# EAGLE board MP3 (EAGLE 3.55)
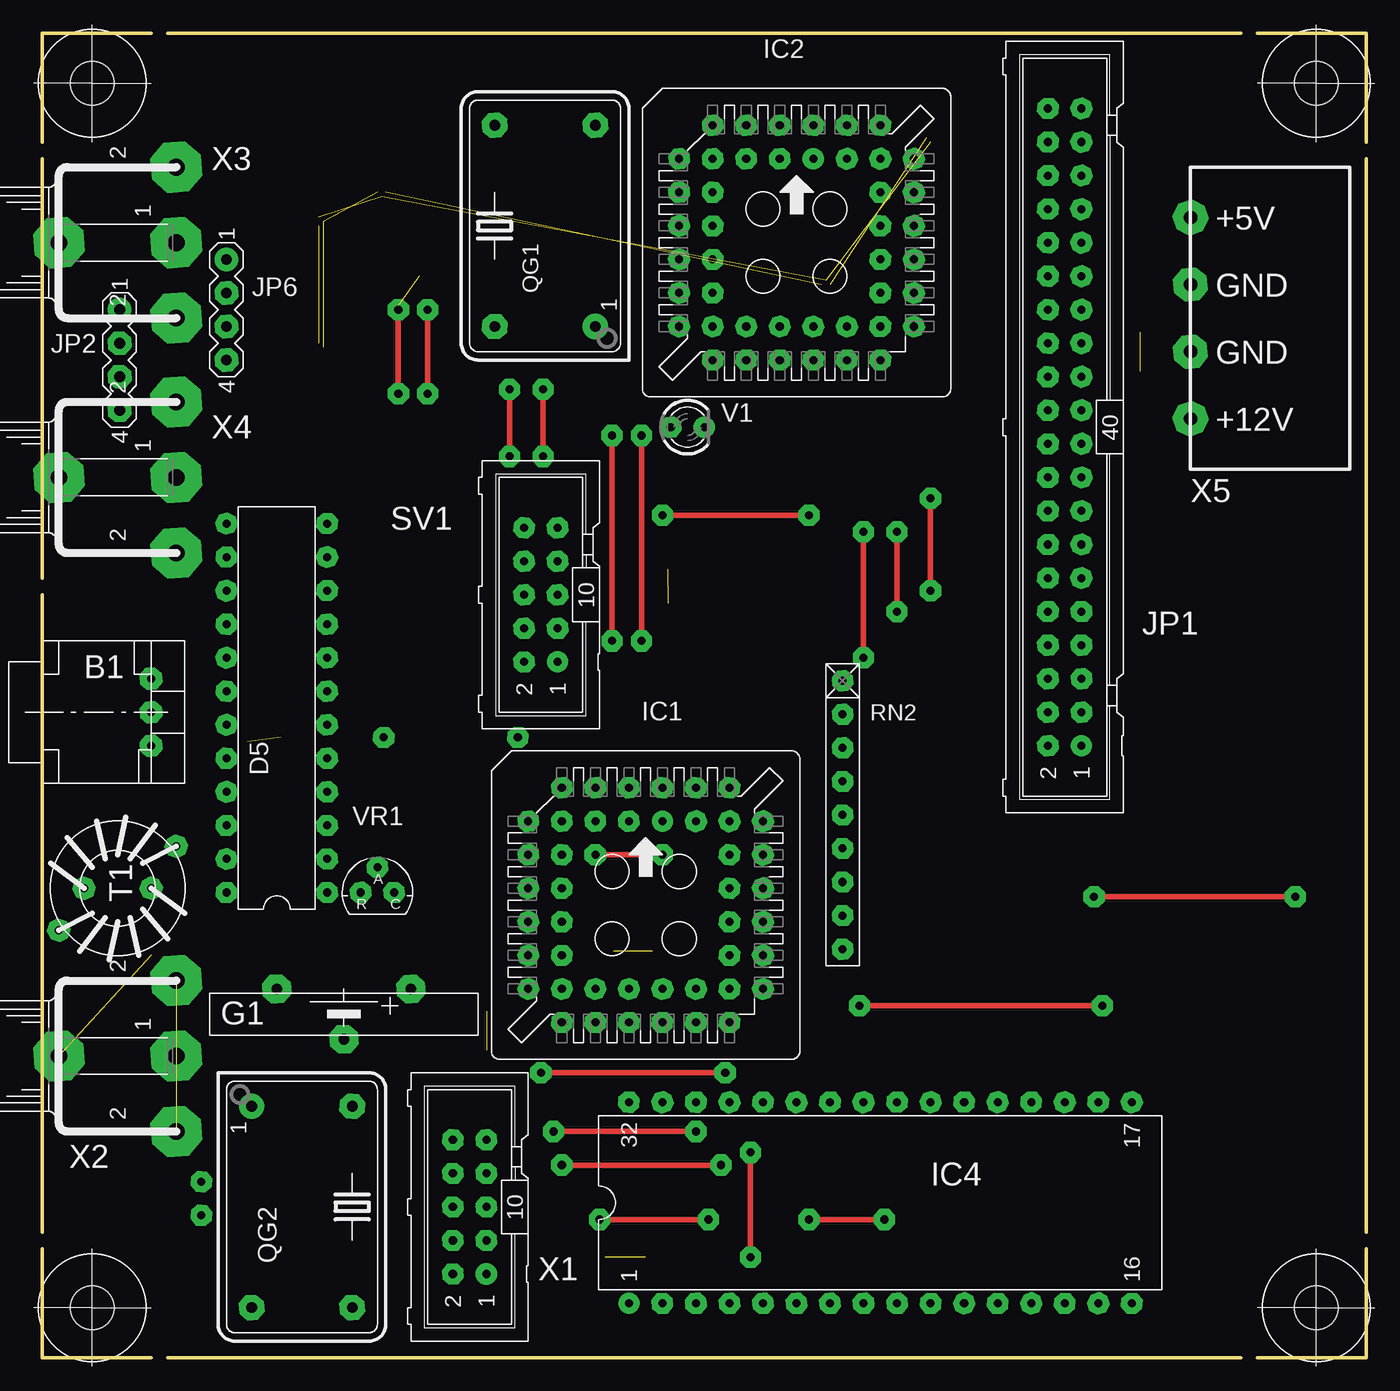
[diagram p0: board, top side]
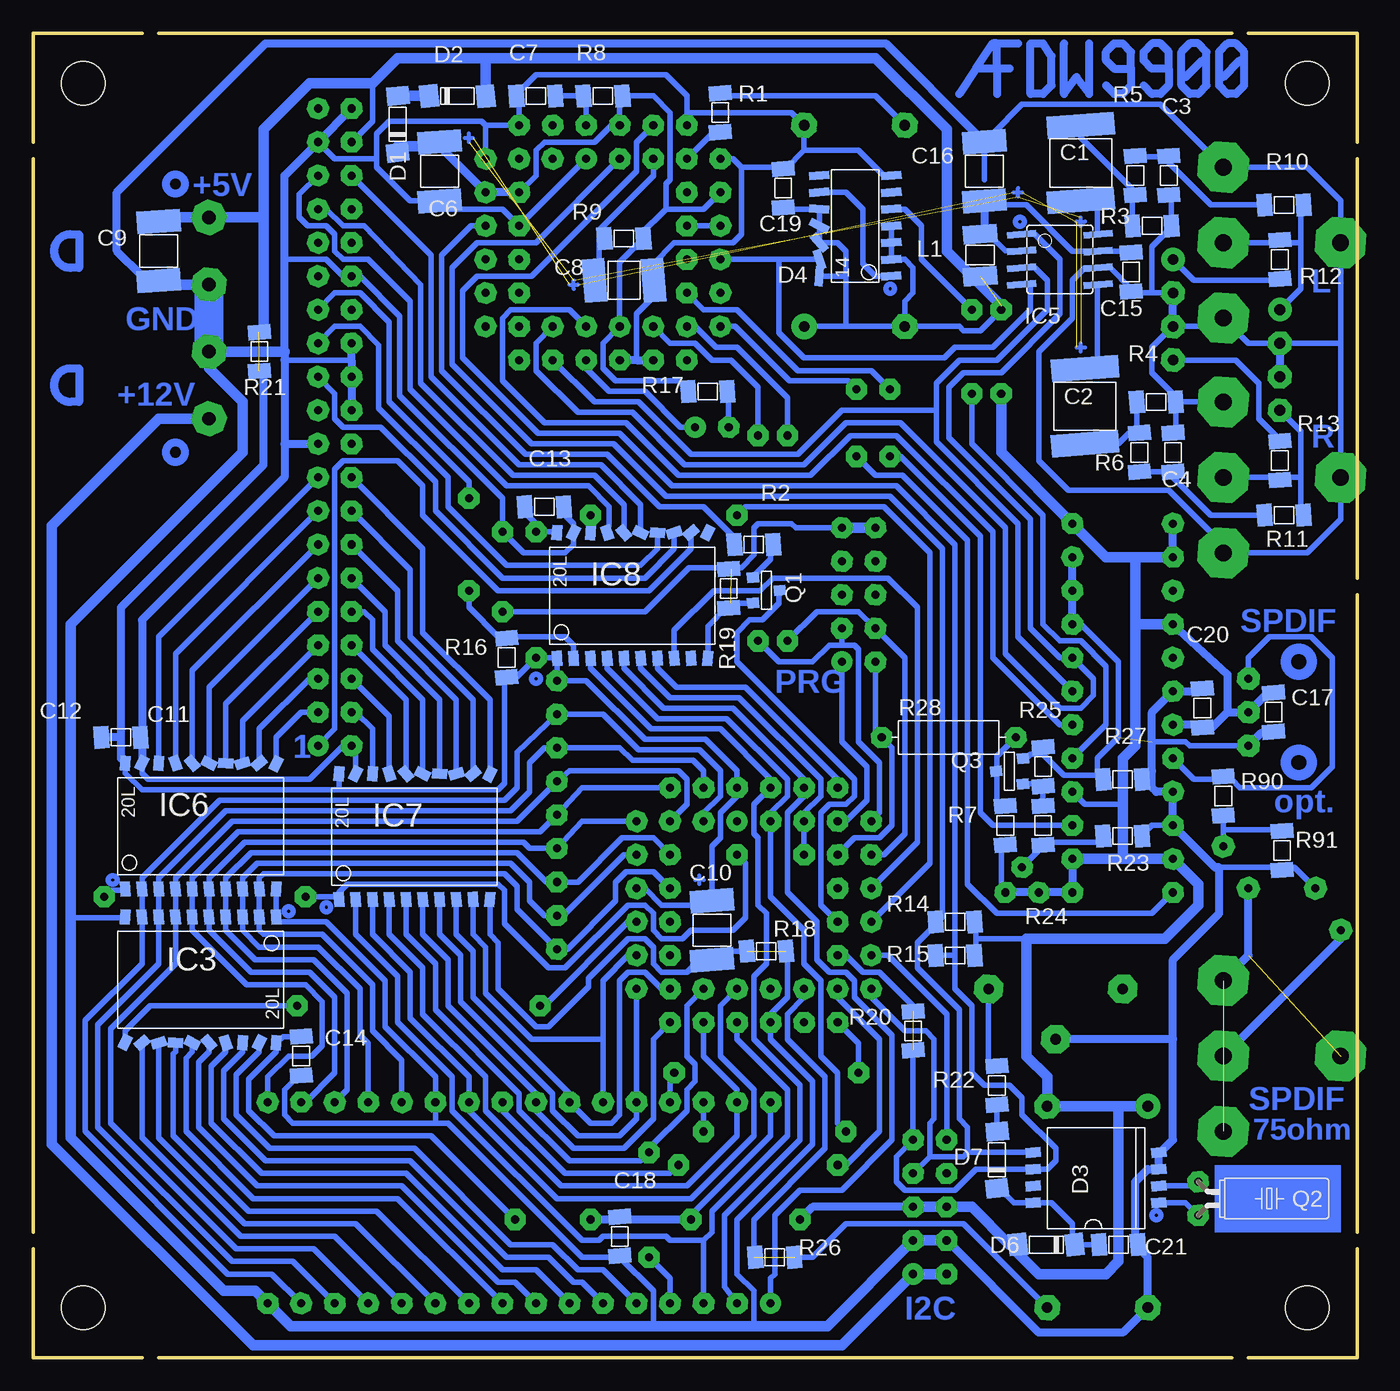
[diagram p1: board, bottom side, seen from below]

Size 100.33 x 100.33 mm. Coordinates in mm from the lower left corner, seen from the top.
Outline: 8.26,0 0,0 0,8.26
Outline: 9.53,0 90.8,0
Outline: 92.07,0 100.33,0 100.33,8.26
Outline: 100.33,9.53 100.33,90.81
Outline: 100.33,92.08 100.33,100.33 92.07,100.33
Outline: 90.8,100.33 9.53,100.33
Outline: 8.26,100.33 0,100.33 0,92.08
Outline: 0,90.81 0,59.05
Outline: 0,57.78 0,9.53
Copper layers used: Top, Bottom

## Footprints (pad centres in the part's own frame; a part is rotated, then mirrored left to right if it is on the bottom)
TX178 = drill 0.61 pad 1.676 octagon:  -2.54,0;  0,0;  2.54,0
20 = smd 1.702 x 5.105 rotated 4.4:  2.845,0 | smd 1.702 x 5.105 rotated 4.3:  -2.845,0
06 = smd 1.143 x 1.702 rotated 4.4:  1.473,0 | smd 1.143 x 1.702 rotated 4.3:  -1.473,0
12 = smd 1.702 x 3.302 rotated 4.4:  2.235,0 | smd 1.702 x 3.302 rotated 4.3:  -2.235,0
D80 = smd 1.397 x 1.702 rotated 6.6:  -2.388,0 | smd 1.397 x 1.702 rotated 5.7:  1.905,-0.025
T176-1 = smd 0.762 x 1.143 rotated 4.3:  -1.905,-4.648 | smd 0.762 x 1.143 rotated 4.4:  -0.635,-4.648 | smd 0.762 x 1.143 rotated 4.5:  0.635,-4.648 | smd 0.762 x 1.143 rotated 4.6:  1.905,-4.648 | smd 0.762 x 1.143 rotated 4.7:  1.905,4.877;  0.635,4.877 | smd 0.762 x 1.143 rotated 4.8:  -0.635,4.877 | smd 0.762 x 1.143 rotated 4.9:  -1.905,4.877
-14 = smd 0.61 x 1.524 rotated 4.3:  -3.81,-2.794;  1.27,2.667 | smd 0.61 x 1.524 rotated 94.3:  -3.81,2.667 | smd 0.61 x 1.524 rotated 4.4:  -2.54,-2.794 | smd 0.61 x 1.524 rotated 4.5:  -1.27,-2.794 | smd 0.61 x 1.524 rotated 71.8:  -2.54,2.667 | smd 0.61 x 1.524 rotated 49.3:  -1.27,2.667 | smd 0.61 x 1.524 rotated 4.6:  0,-2.794 | smd 0.61 x 1.524 rotated 26.8:  0,2.667 | smd 0.61 x 1.524 rotated 4.7:  1.27,-2.794;  2.54,-2.794 | smd 0.61 x 1.524 rotated 5:  2.54,2.667 | smd 0.61 x 1.524 rotated 4.8:  3.81,-2.794 | smd 0.61 x 1.524 rotated 4.9:  3.81,2.667
L24S = drill 0.61 pad 1.6 octagon:  -12.7,-5.08;  -10.16,-5.08;  2.54,-5.08;  5.08,-5.08;  -7.62,-5.08;  -5.08,-5.08;  0,-5.08;  -2.54,-5.08;  7.62,-5.08;  10.16,-5.08;  12.7,-5.08;  15.24,-5.08;  15.24,2.54;  12.7,2.54;  10.16,2.54;  7.62,2.54;  5.08,2.54;  2.54,2.54;  0,2.54;  -2.54,2.54;  -5.08,2.54;  -7.62,2.54;  -10.16,2.54;  -12.7,2.54
32P-V = drill 0.813 pad 2.159 octagon:  -1.905,0;  1.905,-5.08 | drill 0.813 pad 2.184 octagon:  1.905,5.08
CC44 = drill 0.61 pad 1.6 round:  0,0 | drill 0.61 pad 1.6 octagon:  -2.54,2.54;  -2.54,0;  -5.08,2.54;  -5.08,0;  -7.62,2.54;  -10.16,0;  -7.62,0;  -10.16,-2.54;  -7.62,-2.54;  -10.16,-5.08;  -7.62,-5.08;  -10.16,-7.62;  -7.62,-7.62;  -10.16,-10.16;  -7.62,-10.16;  -10.16,-12.7;  -7.62,-15.24;  -7.62,-12.7;  -5.08,-15.24;  -5.08,-12.7;  -2.54,-15.24;  -2.54,-12.7;  0,-15.24;  0,-12.7;  2.54,-15.24;  2.54,-12.7;  5.08,-15.24;  7.62,-12.7;  5.08,-12.7;  7.62,-10.16;  5.08,-10.16;  7.62,-7.62;  5.08,-7.62;  7.62,-5.08;  5.08,-5.08;  7.62,-2.54;  5.08,-2.54;  7.62,0;  5.08,2.54;  5.08,0;  2.54,2.54;  2.54,0;  0,2.54
-20L = smd 0.762 x 1.143 rotated 4.3:  -5.08,-5.131;  6.35,-5.131 | smd 0.762 x 1.143 rotated 4.4:  -3.81,-5.131;  -5.08,4.394 | smd 0.762 x 1.143 rotated 4.5:  -2.54,-5.131 | smd 0.762 x 1.143 rotated 4.6:  -1.27,-5.131 | smd 0.762 x 1.143 rotated 4.7:  0,-5.131;  1.27,-5.131 | smd 0.762 x 1.143 rotated 4.8:  2.54,-5.131 | smd 0.762 x 1.143 rotated 4.9:  3.81,-5.131 | smd 0.762 x 1.143 rotated 5:  5.08,-5.131 | smd 0.762 x 1.143 rotated 49.3:  5.08,4.394 | smd 0.762 x 1.143 rotated 26.8:  6.35,4.369 | smd 0.762 x 1.143 rotated 71.8:  3.81,4.394 | smd 0.762 x 1.143 rotated 94.3:  2.54,4.394 | smd 0.762 x 1.143 rotated 116.8:  1.27,4.394 | smd 0.762 x 1.143 rotated 139.3:  0,4.394 | smd 0.762 x 1.143 rotated 161.8:  -1.27,4.394 | smd 0.762 x 1.143 rotated 184.3:  -2.54,4.394 | smd 0.762 x 1.143 rotated 206.8:  -3.81,4.394
L32 = drill 0.61 pad 1.6 round:  0,0 | drill 0.61 pad 1.6 octagon:  2.54,0;  5.08,0;  7.62,0;  10.16,0;  12.7,0;  15.24,0;  17.78,0;  20.32,0;  22.86,0;  25.4,0;  27.94,0;  30.48,0;  33.02,0;  35.56,0;  38.1,0;  38.1,15.24;  35.56,15.24;  33.02,15.24;  30.48,15.24;  27.94,15.24;  25.4,15.24;  22.86,15.24;  20.32,15.24;  17.78,15.24;  15.24,15.24;  12.7,15.24;  10.16,15.24;  7.62,15.24;  5.08,15.24;  2.54,15.24;  0,15.24
P-8 = smd 0.5 x 2.2 rotated 4.3:  -1.905,-2.9 | smd 0.5 x 2.2 rotated 4.4:  -0.645,-2.9 | smd 0.5 x 2.2 rotated 4.5:  0.625,-2.9 | smd 0.5 x 2.2 rotated 4.6:  1.895,-2.9 | smd 0.5 x 2.2 rotated 4.9:  -1.905,2.9 | smd 0.5 x 2.2 rotated 4.8:  -0.635,2.9 | smd 0.5 x 2.2 rotated 4.7:  0.635,2.9;  1.905,2.9
40 = drill 0.61 pad 1.6 round:  -24.13,-1.27 | drill 0.61 pad 1.6 octagon:  -24.13,1.27;  -21.59,-1.27;  -21.59,1.27;  -19.05,-1.27;  -19.05,1.27;  -16.51,-1.27;  -16.51,1.27;  -13.97,-1.27;  -13.97,1.27;  -11.43,-1.27;  -11.43,1.27;  -8.89,-1.27;  -8.89,1.27;  -6.35,-1.27;  -6.35,1.27;  -3.81,-1.27;  -3.81,1.27;  -1.27,-1.27;  -1.27,1.27;  1.27,-1.27;  1.27,1.27;  3.81,-1.27;  3.81,1.27;  6.35,-1.27;  6.35,1.27;  8.89,-1.27;  8.89,1.27;  11.43,1.27;  11.43,-1.27;  13.97,-1.27;  13.97,1.27;  16.51,1.27;  16.51,-1.27;  19.05,-1.27;  19.05,1.27;  21.59,1.27;  21.59,-1.27;  24.13,-1.27;  24.13,1.27
04-1 = drill 0.813 pad 1.778 round:  -3.81,0 | drill 0.813 pad 1.778 octagon:  -1.27,0;  1.27,0;  3.81,0
10 = smd 1.397 x 2.591 rotated 4.4:  1.6,0 | smd 1.397 x 2.591 rotated 4.3:  -1.6,0
T23EBC = smd 0.787 x 0.889 rotated 5.8:  0.991,1.016 | smd 0.787 x 0.889 rotated 6.1:  -0.94,1.016 | smd 0.787 x 0.889 rotated 5.9:  0.025,-1.016
38H = drill 0.61 pad 1.6 octagon:  -1.27,0;  1.27,0
L14S = drill 0.813 pad 1.905 round:  -7.62,-3.81 | drill 0.813 pad 1.905 octagon:  7.62,-3.81;  7.62,3.81;  -7.62,3.81
10' = drill 0.61 pad 1.6 octagon:  -5.08,0;  5.08,0
-9 = drill 0.61 pad 1.6 octagon:  -10.16,0;  -7.62,0;  -5.08,0;  -2.54,0;  0,0;  2.54,0;  5.08,0;  7.62,0;  10.16,0
10'' = drill 0.61 pad 1.6 round:  -5.08,-1.27 | drill 0.61 pad 1.6 octagon:  -5.08,1.27;  -2.54,-1.27;  -2.54,1.27;  0,-1.27;  0,1.27;  2.54,-1.27;  2.54,1.27;  5.08,-1.27;  5.08,1.27
TB = drill 0.61 pad 1.676 octagon:  0,2.54;  0,-2.54;  3.175,-4.445;  -3.175,4.445
,3 = hole 3.302: 0,0
D3 = drill 0.61 pad 1.6 octagon:  -1.27,0 | drill 0.61 pad 1.6 round:  1.27,0
92-CLP = drill 0.61 pad 1.6 octagon:  -1.27,0;  0,1.905;  1.27,0
NCH = drill 1.27 pad 3.81 octagon:  0,-8.89;  0,0;  5.715,-8.89;  -5.715,-8.89
W5 = drill 1.016 pad 2.54 octagon: 1 -2.54,-5.08; 2 2.54,-5.08; V 7.62,-5.08;  -7.62,-5.08

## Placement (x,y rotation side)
B1  TOTX178  [TX178]  8.26,48.89 270 top
C1  10æ  [20]  20.95,90.49 90 bottom
C2  10æ  [20]  20.64,72.07 270 bottom
C3  680p  [06]  14.29,89.54 270 bottom
C4  680p  [06]  13.97,68.58 270 bottom
C6  10æ  [12]  69.53,89.85 270 bottom
C7  10n  [06]  62.23,95.57 0 bottom
C8  2æ2  [12]  55.56,81.6 180 bottom
C9  10æ  [12]  90.8,83.82 270 bottom
C10  100n//10u  [12]  48.9,32.38 90 bottom
C11  100n  [06]  93.66,46.99 180 bottom
C12  100n  [06]  93.66,46.99 180 bottom
C13  100n  [06]  61.59,64.45 180 bottom
C14  100n  [06]  80.01,22.86 90 bottom
C15  100n  [06]  17.14,82.23 90 bottom
C16  10æ  [12]  28.26,89.85 90 bottom
C17  100n  [06]  6.35,48.89 270 bottom
C18  100n  [06]  55.88,9.21 90 bottom
C19  100n  [06]  43.5,88.58 270 bottom
C20  100n  [06]  11.75,49.21 270 bottom
C21  100n  [06]  18.1,8.57 180 bottom
D1  1N4148  [D80]  72.71,93.66 90 bottom
D2  1N4148  [D80]  67.94,95.57 0 bottom
D3  PCF8583T  [T176-1]  19.68,13.65 90 bottom
D4  74LS113  [-14]  38.1,85.73 90 bottom
D5  CS8402A  [L24S]  16.51,47.94 90 top
D6  1N4148  [D80]  23.81,8.57 180 bottom
D7  1N4148  [D80]  27.3,15.24 90 bottom
G1  BR2032P-V  [32P-V]  22.86,26.04 90 top
IC1  AT89S8252  [CC44]  46.99,40.64 0 top
IC2  MAS3507D  [CC44]  58.42,90.81 0 top
IC3  74HC573  [-20L]  86.99,28.26 180 bottom
IC4  628128/512  [L32]  44.45,4.13 0 top
IC5  CS4331  [P-8]  22.54,83.19 270 bottom
IC6  74HCT245  [-20L]  88.27,40.64 0 bottom
IC7  74HCT245  [-20L]  72.07,39.85 0 bottom
IC8  74HCT245  [-20L]  55.56,58.1 0 bottom
JP1  IDE_CON  [40]  77.47,70.48 90 top
JP2  OUT  [04-1]  5.87,75.56 270 top
JP6  CD_IN  [04-1]  13.97,79.38 270 top
L1  100æH  [10]  28.57,83.5 90 bottom
Q1  BC548  [T23EBC]  44.77,58.1 90 bottom
Q2  32.768kHz  [38H]  12.06,12.07 270 bottom
Q3  BC548  [T23EBC]  26.35,44.45 270 bottom
QG1  14,318Mhz  [L14S]  38.1,85.73 90 top
QG2  24Mhz  [L14S]  19.68,11.43 270 top
R1  470  [06]  48.26,94.3 270 bottom
R2  10k  [06]  45.72,61.59 0 bottom
R3  56k  [06]  15.56,85.73 0 bottom
R4  56k  [06]  15.24,72.39 180 bottom
R5  2k2  [06]  16.83,89.54 90 bottom
R6  2k2  [06]  16.51,68.58 270 bottom
R7  10k  [06]  26.67,40.32 270 bottom
R8  10k  [06]  57.15,95.57 0 bottom
R9  1k  [06]  55.56,84.77 0 bottom
R10  10k  [06]  5.56,87.31 0 bottom
R11  10k  [06]  5.56,63.82 0 bottom
R12  10k  [06]  5.87,83.19 270 bottom
R13  10k  [06]  5.87,67.95 90 bottom
R14  10k  [06]  30.48,33.02 0 bottom
R15  10k  [06]  30.48,30.48 0 bottom
R16  10k  [06]  64.45,53.02 270 bottom
R17  1k  [06]  49.21,73.18 180 bottom
R18  0  [06]  44.77,30.8 0 bottom
R19  0  [06]  47.62,58.26 270 bottom
R20  0  [06]  33.66,24.77 90 bottom
R21  0  [06]  83.18,76.2 270 bottom
R22  470k  [06]  27.3,20.64 90 bottom
R23  3k3  [06]  17.78,39.53 180 bottom
R24  47k  [06]  23.81,40.32 90 bottom
R25  33k  [06]  23.81,44.77 270 bottom
R26  0  [06]  44.13,7.62 0 bottom
R27  0  [06]  17.78,43.81 0 bottom
R28  10k  [10']  30.96,46.99 0 bottom
R90  390  [06]  10.16,42.54 270 bottom
R91  91  [06]  5.71,38.42 270 bottom
RN2  10k  [-9]  60.64,41.12 270 top
SV1  ML10  [10'']  37.78,57.78 90 top
T1  RIK 10  [TB]  5.71,35.56 270 top
U$3  [,3]  96.52,96.52 0 top
U$4  [,3]  96.52,3.81 0 top
U$5  [,3]  3.81,3.81 0 top
U$6  [,3]  3.81,96.52 0 top
V1  LED 3 gn  [D3]  48.9,70.48 0 top
VR1  TL431CLP  [92-CLP]  25.4,35.24 0 top
X1  ML10  [10'']  32.39,11.43 90 top
X2  RCA  [NCH]  1.27,22.86 90 top
X3  RCA  [NCH]  1.27,84.45 90 top
X4  RCA  [NCH]  1.27,66.67 90 top
X5  PSW5  [W5]  92.07,78.74 270 top

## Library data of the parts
B1 D1-D3 D5 G1 Q1 T1 X2-X5 = walter
C1-C4 C6-C19 L1 R1-R18 R90 R91 = smd
C20 C21 R19-R28 RN2 = DISCRETE
D4 IC3 IC5-IC7 = smd-ic
D6 D7 = diode
IC1 IC2 IC4 = mp3
IC8 = 74XX
JP1 SV1 X1 = con-ml
JP2 JP6 = CON-LSTB
Q2 QG1 QG2 = QUARTZ
Q3 = TRANS-SM
U$3-U$6 = holes
V1 = LED
VR1 = v-reg

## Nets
3,3V: C6. D1. IC2. R8. R9. R17.
24MHZ: IC1. QG2. R26.
+: G1.
+12V: X1. X5.V
/POR: C8. IC2. R9.
A0: IC3. IC4.
A1: IC3. IC4.
A2: IC3. IC4.
A3: IC3. IC4.
A4: IC3. IC4.
A5: IC3. IC4.
A6: IC3. IC4.
A7: IC3. IC4.
AD0: IC1. IC3. IC4. IC6. RN2.
AD1: IC1. IC3. IC4. IC6. RN2.
AD2: IC1. IC3. IC4. IC6. RN2.
AD3: IC1. IC3. IC4. IC6. RN2.
AD4: IC1. IC3. IC4. IC6. RN2.
AD5: IC1. IC3. IC4. IC6. RN2.
AD6: IC1. IC3. IC4. IC6. RN2.
AD7: IC1. IC3. IC4. IC6. RN2.
AD8: IC1. IC4. IC7.
AD9: IC1. IC4. IC7.
AD10: IC1. IC4. IC7.
AD11: IC1. IC4. IC7.
AD12: IC1. IC4. IC7.
AD13: IC1. IC4. IC7.
AD14: IC1. IC4. IC7.
AD15: IC1. IC4. IC7.
AOUT_L: JP2. R10. R12. X3.
AOUT_R: JP2. R11. R13. X4.
CLKI: IC2. R1.
CLKO: D4. IC2. IC5.
DCEN: C7. IC2. R8.
FC0: D5. IC2.
FC1: D5. IC2.
FILT+: C15. C16. IC5. L1.
FSYNC: D5. IC2. IC5.
GND: B1. C3. C4. C6. C7. C8. C9. C10. C11. C12. C13. C14. C15. C16. C17. C18. C19. C20. C21. D3. D4. D5. G1. IC1. IC2. IC3. IC4. IC5. IC6. IC7. IC8. JP1. JP2. JP6. Q1. Q3. QG1. QG2. R3. R4. R18. R19. R23. R25. R27. R91. SV1. T1. X1. X3. X4. X5.1 X5.2
IDE_ADR0: IC1. IC4. IC8.
IDE_ADR1: IC1. IC4. IC8.
IDE_ADR2: IC1. IC4. IC8.
IDE_ICHR: IC1. IC8.
IDE_IOR: IC1. IC6. IC7. IC8.
IDE_IOW: IC1. IC8.
IDE_RES: IC1. IC8.
INT: IC1. X1.
MAS_DEM: IC2. R2.
MAS_SIC: IC1. IC2. SV1.
MAS_SID: IC1. IC2. SV1.
MCK: D4. D5.
MEM_/RD: IC1. IC4.
MEM_/WR: IC1. IC4.
MEM_ALE: IC1. IC3.
MISO: IC1. SV1.
N$1: IC8. JP1.
N$2: IC8. JP1.
N$3: IC8. JP1. R16.
N$4: C1. IC5.
N$5: C2. IC5.
N$6: C1. R3. R5.
N$7: C2. R4. R6.
N$8: C3. R5. R10.
N$9: C4. R6. R11.
N$10: IC7. JP1.
N$12: IC7. JP1.
N$13: IC7. JP1.
N$14: IC7. JP1.
N$15: IC7. JP1.
N$16: IC7. JP1.
N$17: IC2.
N$18: IC1. Q1.
N$19: IC8. JP1.
N$20: IC7. JP1.
N$21: Q1. R2.
N$22: QG1. R1.
N$23: D4.
N$24: IC7. JP1.
N$25: IC6. JP1.
N$26: IC6. JP1.
N$27: IC6. JP1.
N$28: IC6. JP1.
N$29: IC6. JP1.
N$30: IC6. JP1.
N$31: IC6. JP1.
N$32: IC6. JP1.
N$33: IC8. JP1.
N$34: IC8. JP1.
N$35: IC8. JP1.
N$38: D3. Q2.
N$39: D3. Q2.
N$41: D1. D2.
N$42: R23. R24. VR1.
N$44: D7. R22.
N$45: Q3. R24. R25.
N$52: JP6. R12.
N$54: JP6. R13.
N$56: R17. V1.
N$59: R90. R91. T1.
N$61: Q3. R7. R28.
PI8: IC2. V1.
RES: IC1. R28. SV1.
SCK: D5. IC2.
SCL: D3. IC1. IC2. R15. R20. X1.
SDA: D3. IC1. IC2. R14. X1.
SDATA: D5. IC2. IC5.
SPDIF+: T1. X2.
SPDIF-: T1. X2.
TXP: B1. D5. R90.
U_BATT: G1. R22.
U_RTC: C21. D3. D6. D7.
VCC: B1. C9. C10. C11. C12. C13. C14. C17. C18. C19. C20. D2. D4. D5. D6. IC1. IC3. IC4. IC6. IC7. IC8. JP1. L1. QG1. QG2. R7. R14. R15. R16. R21. RN2. VR1. X1. X5.

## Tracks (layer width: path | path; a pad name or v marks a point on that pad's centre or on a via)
3,3V
  Bottom 0.406: 48.26,88.27 49.53,87 52.39,87 | 52.39,87 52.39,88.9 52.07,89.22 52.07,94.3 53.34,95.57 55.68,95.57 55.88,95.57 55.88,93.34 56.52,93.34 57.79,92.08 61.59,92.08 62.23,91.44 62.23,89.54 63.5,88.27 | 52.39,87 54.29,85.09 54.29,84.77 54.09,84.77 55.88,82.98 55.88,78.11 57.15,76.84 57.15,74.93 56.2,73.98 51.44,73.98 50.64,73.18 50.69,73.18 | 69.53,91.76 C6. | 72.71,91.76 72.71,91.28
  Bottom 0.61: 63.5,88.27 66.04,88.27 69.53,91.76
  Bottom 0.813: 69.53,91.76 72.71,91.76
24MHZ  (2 unrouted)
  Bottom 0.406: 41.91,27.94 41.91,27.3 43.18,26.04 43.18,24.13 40.32,21.27 40.32,15.88 45.72,10.48 45.72,7.62 | 23.49,3.81 29.84,10.16 38.73,10.16 41.27,7.62 42.66,7.62
+12V
  Bottom 0.813: 31.11,6.35 33.66,6.35 39.05,0.95 83.66,0.95 98.9,16.19 98.9,63.02 90.8,71.12 X5.V
/POR
  Bottom 0.406: 57.8,81.6 57.47,81.59 57.47,84.66 R9. 57.47,84.89 57.47,85.41 53.34,89.54 53.34,90.81
A0
  Bottom 0.406: 92.07,23.86 92.07,16.67 84.61,9.21 77.47,9.21 72.39,4.13
A1
  Bottom 0.406: 90.8,23.86 90.8,16.67 84.3,10.16 75.88,10.16 69.85,4.13
A2
  Bottom 0.406: 89.53,23.86 89.53,23.18 89.69,23.02 89.69,16.83 83.98,11.11 74.3,11.11 67.31,4.13
A3
  Bottom 0.406: 88.27,23.86 88.27,23.18 88.74,22.7 88.74,17.14 83.66,12.07 72.71,12.07 64.77,4.13
A4
  Bottom 0.406: 86.99,23.86 86.99,23.18 87.79,22.38 87.79,17.46 83.34,13.02 72.39,13.02 65.09,5.71 63.82,5.71 62.23,4.13
A5
  Bottom 0.406: 85.72,23.86 85.72,23.18 86.84,22.07 86.84,17.78 83.03,13.97 72.07,13.97 64.77,6.67 62.23,6.67 59.69,4.13
A6
  Bottom 0.406: 84.45,23.86 84.45,23.18 85.88,21.75 85.88,18.1 82.71,14.92 71.75,14.92 64.45,7.62 61.28,7.62 59.37,5.71 58.74,5.71 57.15,4.13
A7
  Bottom 0.406: 83.18,23.86 83.18,23.18 84.93,21.43 84.93,18.41 82.39,15.88 71.44,15.88 64.13,8.57 60.96,8.57 59.05,6.67 57.15,6.67 54.61,4.13
AD0
  Bottom 0.406: 49.53,40.64 49.53,41.27 48.26,42.54 48.26,44.45 49.85,46.04 54.45,46.04 57.15,48.74 60.64,48.74 63.66,45.88 63.66,43.18 64.61,42.23 86.2,42.23 92.07,36.35 92.07,35.51 92.07,33.39 92.07,29.84 96.36,25.56 96.36,17.14 85.57,6.35 82.23,6.35 80.01,4.13
AD1
  Bottom 0.406: 49.53,43.18 49.53,44.45 50.32,45.24 54.93,45.24 55.88,46.2 60.64,46.2 61.59,46.2 62.71,45.08 62.71,42.86 64.13,41.43 67.94,41.43 76.99,41.43 77.63,41.43 85.72,41.43 90.8,36.35 90.8,35.51 90.8,33.39 90.8,29.84 95.41,25.24 95.41,17.46 85.25,7.3 80.64,7.3 77.47,4.13
AD2
  Bottom 0.254: 89.53,33.39 89.53,33.34
  Bottom 0.406: 52.07,40.64 50.8,41.91 50.8,43.81 51.44,44.45 59.69,44.45 60.64,43.66 63.66,40.64 85.25,40.64 89.53,36.35 89.53,35.51 89.53,33.39 89.53,29.84 94.46,24.92 94.46,17.78 84.93,8.26 79.06,8.26 74.93,4.13
AD3
  Bottom 0.254: 88.27,33.34 88.27,33.39
  Bottom 0.406: 82.55,19.37 82.55,21.27 80.96,22.86 79.22,22.86 78.42,23.65 78.42,26.99 79.69,28.26 84.14,28.26 88.27,32.38 88.27,33.34 88.27,35.51 88.27,36.35 84.77,39.85 78.26,39.85 77.63,39.85 61.91,39.85 60.64,41.12 | 60.64,41.12 | 52.07,43.18 58.74,43.18 60.64,41.12
AD4
  Bottom 0.254: 86.99,33.34 86.99,33.39
  Bottom 0.406: 80.01,19.37 79.69,19.37 77.47,21.59 77.47,27.3 79.38,29.21 83.82,29.21 86.99,32.38 86.99,33.34 86.99,35.51 86.99,36.35 84.3,39.05 78.58,39.05 77.95,39.05 64.93,39.05 63.18,39.05 62.71,38.58 60.64,38.58 58.74,40.64 54.61,40.64
AD5
  Bottom 0.254: 85.72,33.34 85.72,33.39
  Bottom 0.406: 52.07,38.1 53.34,39.37 55.72,39.37 59.05,36.04 60.64,36.04 61.44,36.04 63.66,38.26 65.09,38.26 78.26,38.26 78.9,38.26 83.82,38.26 85.72,36.35 85.72,35.51 85.72,33.34 85.72,32.38 83.5,30.16 79.06,30.16 76.52,27.62 76.52,20.32 77.47,19.37
AD6
  Bottom 0.254: 84.45,33.34 84.45,33.39
  Bottom 0.406: 74.93,19.37 74.93,23.81 75.56,24.45 75.56,27.94 78.74,31.11 83.18,31.11 84.45,32.38 84.45,33.34 84.45,35.51 84.45,36.35 83.34,37.46 64.13,37.46 62.71,36.04 62.71,34.61 61.59,33.5 60.64,33.5 60.17,33.5 55.56,38.1 54.61,38.1
AD7
  Bottom 0.406: 52.07,35.56 53.34,36.83 55.4,36.83 56.2,36.04 56.2,34.61 59.85,30.96 RN2. | 72.39,19.37 72.39,22.54 74.61,24.77 74.61,28.26 78.42,32.07 82.87,32.07 83.18,32.38 83.18,33.39 83.18,35.51 83.18,36.35 82.87,36.67 78.9,36.67 66.52,36.67 64.61,36.67 | RN2. | RN2. 63.66,33.97 63.66,35.72 64.61,36.67 | 64.61,36.67 64.77,36.67
AD8
  Bottom 0.406: 49.53,8.89 52.07,8.89 52.39,9.21 57.15,9.21 57.47,8.89 58.74,8.89 68.58,18.73 68.58,21.27 72.71,25.4 72.71,28.89 75.88,32.07 75.88,34.72 | 49.53,8.89 48.9,9.53 48.9,11.11 43.18,16.83 43.18,20.32 46.99,24.13 46.99,25.4 | 49.53,4.13 49.53,8.89
AD9
  Bottom 0.406: 46.99,27.94 48.26,26.67 48.26,22.86 45.72,20.32 45.72,16.83 50.48,12.07 60.64,12.07 67.31,18.73 67.31,19.05 | 67.31,19.05 67.31,19.37 | 67.31,19.05 67.31,21.27 71.75,25.72 71.75,29.21 74.61,32.07 74.61,34.72
AD10
  Bottom 0.406: 49.53,25.4 49.53,22.86 46.99,20.32 46.99,19.37 46.99,16.83 50.8,13.02 60.33,13.02 66.04,18.73 66.04,21.27 70.8,26.04 70.8,29.53 73.34,32.07 73.34,34.72
AD11  (via drill 0.61 pad 1.6)
  Top 0.406: v53.66,7.62 v53.66,15.56
  Bottom 0.406: 49.53,27.94 50.8,26.67 50.8,22.86 50.16,22.23 50.16,20.96 50.8,20.32 50.8,18.73 53.66,15.88 v53.66,15.56 54.29,14.92 59.69,14.92 63.5,18.73 63.5,20 69.85,26.35 69.85,29.84 72.07,32.07 72.07,34.72 | 52.07,4.13 52.07,6.03 v53.66,7.62
AD12
  Bottom 0.406: 52.07,25.4 53.34,24.13 53.34,18.1 55.56,15.88 59.37,15.88 62.23,18.73 62.23,19.37 62.23,20 68.9,26.67 68.9,30.16 70.8,32.07 70.8,34.72
AD13
  Bottom 0.406: 54.61,27.94 54.61,19.37 54.61,18.1 55.88,16.83 59.05,16.83 60.96,18.73 60.96,20 67.94,26.99 67.94,30.48 69.53,32.07 69.53,34.72
AD14
  Bottom 0.406: 52.07,27.94 52.71,27.94 53.98,29.21 55.25,29.21 55.88,28.57 55.88,18.41 56.52,17.78 58.1,17.78 59.69,19.37 59.69,20 66.99,27.3 66.99,30.8 68.26,32.07 68.26,34.72
AD15
  Bottom 0.406: 57.15,19.37 57.15,24.13 | 57.15,24.13 57.15,28.57 55.25,30.48 54.61,30.48 | 57.15,24.13 62.55,24.13 66.04,27.62 66.04,31.11 66.99,32.07 66.99,34.72
AOUT_L
  Bottom 0.406: 5.87,79.38 4.29,80.96 4.29,84.45 | 4.29,84.45 4.29,86.04 | 4.08,87.31 4.29,87.15 4.29,86.04 | R12. 6.03,84.66 6.03,84.45 10.16,84.45 | 4.29,86.04 4.29,84.45 | R12. | 4.29,84.45 5.87,84.45 R12.
AOUT_R
  Bottom 0.406: JP2. 4.29,70.17 4.29,66.67 | 10.16,66.67 6.19,66.67 5.99,66.47 R13. 5.87,66.67 4.29,66.67 | 4.08,63.82 4.08,63.93 4.29,64.14 4.29,66.67
CLKI
  Bottom 0.406: 50.8,90.81 48.9,92.71 48.58,92.71 48.46,92.82 48.26,92.82
CLKO
  Bottom 0.406: 40.64,83.19 40.77,83.19 43.82,83.19 | 43.82,83.19 48.26,83.19 | 43.82,83.19 43.82,77.63 41.91,75.72 31.27,75.72 30.48,76.52 27.62,76.52 24.76,79.38 24.76,81.28 25.44,81.29
DCEN
  Bottom 0.406: IC2. 58.42,95.57 R8. 60.76,95.57
FC0  (via drill 0.61 pad 1.6)
  Top 0.406: v35.4,68.26 v35.4,73.34
  Bottom 0.406: 50.8,80.65 49.53,79.38 46.99,79.38 42.39,74.77 36.83,74.77 v35.4,73.34 | v35.4,68.26 34.61,68.26 28.57,62.23 28.57,41.27 27.62,40.32 21.59,40.32
FC1  (via drill 0.61 pad 1.6)
  Top 0.406: v37.94,68.26 v37.94,73.34
  Bottom 0.406: 48.26,78.11 47.15,78.11 43.02,73.98 38.58,73.98 v37.94,73.34 | v37.94,68.26 36.51,66.83 34.45,66.83 29.53,61.91 29.53,35.88 27.3,33.65 15.56,33.65 D5.
FILT+
  Bottom 0.406: 17.14,83.71 17.14,83.82 19.64,83.82 21.59,83.82 25.08,87.31 28.26,87.31 C16. | 28.26,85.41 28.56,85.1 28.57,85.1 28.57,85.09 27.94,85.09 26.68,83.83 25.44,83.83
  Bottom 0.61: 28.26,87.31 28.26,85.41
FSYNC
  Bottom 0.406: 21.59,50.48 25.72,54.61 25.72,63.18 31.91,69.37 31.91,71.76 | 31.91,71.76 39.05,71.76 42.39,68.42 50.48,68.42 54.45,72.39 57.79,72.39 60.96,75.56 | 31.91,73.82 30.16,75.56 27.3,75.56 23.49,79.38 23.49,81.6 24.45,82.55 25.4,82.55 25.41,82.56 25.44,82.56 | 31.91,73.82 | 31.91,71.76 31.91,73.82
GND  (via drill 0.61 pad 1.6)  (3 unrouted)
  Top 0.406: v64.77,62.55 v64.77,56.51
  Bottom 0.254: 81.6,33.02 81.91,33.39 | 76.2,81.92 75.56,81.92
  Bottom 0.406: 81.91,33.39 81.91,35.51 | 81.6,33.02 78.1,33.02 73.66,28.57 73.66,25.08 69.85,21.27 69.85,19.37 69.85,17.78 | 69.85,17.78 68.9,17.78 58.74,7.62 55.88,7.62 | 76.2,81.92 76.83,81.92 78.1,83.19 81.28,83.19 | 75.56,81.92 72.55,78.9 72.55,72.87 64.77,65.09 v64.77,62.55 63.18,60.96 60.01,60.96 59.37,61.59 59.37,62.5 59.37,63.18 60.01,63.82 60.01,64.14 60.12,64.25 C13. | 41.91,91.44 43.29,90.06 C19. 43.61,90.06 43.82,89.85 44.13,90.17 46.67,90.17 | 41.91,91.44 41.91,93.34 42.86,94.3 50.8,94.3 | 41.91,91.44 37.78,91.44 35.88,89.54 35.31,89.54 | 93.34,33.39 93.34,33.34 97.47,33.34 | 92.07,47.31 92.19,47.19 | 92.07,45.03 92.07,44.29 91.6,43.81 79.38,43.81 76.83,46.35 76.2,46.35 75.88,46.35 75.88,44.24 | 69.85,17.78 80.64,17.78 81.28,18.41 81.28,20.32 80.21,21.39 C14. | 54.61,75.56 54.61,79.06 53.33,80.34 C8. 53.33,81.9 53.34,81.92 53.34,82.87 51.75,84.45 47.31,84.45 46.67,85.09 46.67,90.17 | 48.26,90.81 47.31,90.81 46.67,90.17 | 58.42,90.81 63.5,85.73 64.77,87 69.53,87 69.53,87.62 69.84,87.62 69.85,87.63 71.75,87.63 74.3,90.17 74.3,90.81 | 50.8,94.3 50.8,93.34 | 78.74,92.08 77.47,90.81 74.3,90.81 | 74.3,90.81 74.3,92.71 73.34,93.66 66.36,93.66 66.04,93.34 | 66.04,93.34 63.5,93.34 63.5,95.57 C7. 63.7,95.68 62.23,97.16 52.39,97.16 50.8,95.57 50.8,94.3 | 66.04,93.34 66.04,90.81 | v64.77,56.51 53.98,56.51 50.64,59.85 47.94,59.85 47.83,59.73 R19. 47.42,59.73 47.31,59.85 46.67,59.85 45.72,60.8 45.72,62.87 45.4,63.18 42.86,63.18 42.55,62.87 39.05,62.87 | 49.21,52.97 49.21,55.4 47.83,56.79 47.62,56.79 47.51,56.79 47.47,56.99 47.45,57.16 45.78,57.16 | 28.89,92.71 27.94,92.71
  Bottom 0.406: 27.94,92.71 27.62,92.71 25.4,94.93 14.92,94.93 10.16,90.17 3.81,90.17 1.27,87.63 1.27,84.45 1.27,76.84 | 1.27,76.84 1.27,66.67 1.27,63.5 3.81,60.96 X4. 10.16,61.59 14.29,65.72 21.91,65.72 24.13,67.95 24.13,76.2 21.59,78.74 21.59,81.6 20.64,82.55 19.64,82.55 18.73,82.55 17.14,80.96 C15. 17.14,80.65 15.56,80.65 | R18. 48.58,30.8 48.59,30.79 C10. 49.2,30.79 49.21,30.8 50.8,29.21 52.71,29.21 53.34,29.84 53.34,31.11 53.98,31.75 55.25,31.75 58.26,28.73 58.26,28.1 61.28,25.08 62.23,25.08 65.09,27.94 65.09,31.43 65.72,32.07 65.72,34.72 | 43.29,30.8 43.29,30.59 43.18,30.48 43.18,27.3 44.45,26.04 44.45,25.4 44.45,24.13 41.27,20.96 41.27,16.19 46.99,10.48 46.99,6.35 45.72,5.08 45.72,2.38 | R4. 10.16,72.39 | C4. 13.77,70.05 13.65,70.17 13.77,70.28 R4. | 13.97,80.65 15.56,80.65 | 5.87,76.84 8.26,76.84 X3. 10.79,78.11 13.97,78.11 15.56,76.52 15.56,74.61 13.97,73.03 13.97,72.71 13.77,72.5 R4. | 5.87,76.84 | 15.56,80.65 15.56,84.14 14.08,85.61 14.08,85.73 14.08,87.74 14.29,87.95 14.29,88.06 | 28.26,92.08 28.26,92.09 27.94,92.71 | 1.27,76.84 5.87,76.84 | 53.34,2.38 53.34,5.08 55.88,7.62 | 55.88,7.62 C18. | 21.59,55.56 20.95,55.56 18.1,52.7 18.1,46.99 19.68,45.4 19.68,44.13 | 15.04,14.29 14.92,14.29 15.04,14.4 | 16.83,8.89 16.62,8.69 C21. 16.62,8.37 | 19.68,44.13 22.22,44.13 23.81,45.72 | 23.81,45.72 R25. | 25.34,45.39 25.09,45.39 24.76,45.72 23.81,45.72 | 15.04,15.56 14.92,15.56 | 15.56,46.67 13.02,46.67 12.7,46.35 B1. | 12.06,50.48 11.86,50.69 C20. | 3.17,35.56 4.76,37.15 5.4,37.15 5.6,36.94 5.71,36.94 5.71,37.15 10.48,37.15 | 6.67,47.31 6.55,47.42 6.35,47.42 | 13.97,40.32 15.56,40.32 16.35,39.53 R23.
  Bottom 0.406: 81.28,75.56 76.2,75.56 | R27. 19.37,43.81 19.68,44.13 | 16.31,43.81 16.19,43.81 16.19,44.45 15.56,44.45
  Bottom 0.61: 76.2,76.84 76.2,75.56 76.2,74.3 76.2,71.76 | 81.28,69.22 78.74,69.22 | JP1. 78.74,92.08 81.28,89.54 81.28,83.19 81.28,76.2 81.28,75.56 81.28,69.22 | 55.88,75.56 54.61,75.56 53.34,75.56 | 21.59,60.64 21.59,58.1 21.59,55.56 | 31.11,8.89 24.13,1.9 17.78,1.9 15.88,3.81 15.88,7.62 16.62,8.37 | 92.07,45.03 92.07,46.67 92.19,46.79 C12. 92.19,47.19 | 81.28,69.22 81.28,66.67 92.07,55.88 92.07,47.31 | 28.89,92.71 35.72,99.54 82.71,99.54 93.98,88.27 93.98,83.82 92.07,81.92 90.8,81.92 90.8,81.59 90.8,81.28 | 13.97,78.11 13.97,80.65 | 5.87,76.84 5.87,74.3 | 15.04,14.4 15.04,15.56 | 15.04,14.29 15.88,14.29 16.83,13.34 16.83,8.89 | 13.97,24.13 22.86,24.13 | 13.97,24.13 13.97,16.51 14.92,15.56 | 12.06,50.48 13.97,50.48 15.56,48.89 15.56,46.67 15.56,44.45 15.56,43.18 15.24,42.86 13.97,42.86 13.97,40.32 10.79,37.15 10.48,37.15 10.48,33.65 13.97,30.16 13.97,24.13 | B1. 7.3,47.31 6.67,47.31 | 86.99,74.93 X5.2
  Bottom 0.813: 31.11,8.89 33.66,8.89 40.16,2.38 45.72,2.38 53.34,2.38 80.8,2.38 82.55,4.13 83.5,5.08 85.88,5.08 97.47,16.67 97.47,33.34 97.47,55.56 84.45,68.58 84.45,72.39 86.99,74.93 | 39.05,62.87 SV1. | X5.1 90.8,81.28 | X5.2 81.28,76.2
  Bottom 2.184: X5.2 X5.1
IDE_ADR0
  Bottom 0.406: 58.1,53.02 58.1,52.97 58.1,52.23 53.5,47.62 48.26,47.62 44.45,43.81 44.45,43.18 45.72,41.91 45.72,39.69 45.4,39.37 45.4,34.29 44.77,33.65 44.77,29.84 45.72,28.89 45.72,24.13 42.23,20.64 42.23,16.51 47.94,10.79 47.94,5.4 46.99,4.13
IDE_ADR1  (via drill 0.61 pad 1.6)
  Top 0.406: v38.73,17.14 v49.53,17.14
  Bottom 0.254: 44.45,40.64 44.45,41.27 | 56.83,52.97 56.83,53.02
  Bottom 0.406: 44.45,40.64 44.45,34.92 41.91,32.38 41.91,29.84 40.64,28.57 40.64,22.86 39.37,21.59 39.37,17.78 v38.73,17.14 | 44.45,41.27 43.18,42.54 43.18,43.81 47.78,48.42 53.02,48.42 56.83,52.23 56.83,52.97 | v49.53,17.14 49.53,19.37
IDE_ADR2
  Bottom 0.406: 55.56,53.02 55.56,52.97 55.56,52.23 52.55,49.21 47.31,49.21 41.91,43.81 41.91,43.18 41.91,42.54 43.18,41.27 43.18,35.24 40.96,33.02 40.96,30.16 40.01,29.21 38.73,29.21 38.1,28.57 38.1,27.3 35.24,24.45 35.24,16.51 39.05,12.7 42.23,12.7 44.13,10.79 44.13,6.35 44.45,6.03 44.45,4.13
IDE_ICHR  (via drill 0.61 pad 1.6)
  Top 0.406: v46.99,63.82 v58.1,63.82
  Bottom 0.406: 36.83,33.02 32.39,37.46 32.39,60.96 35.88,64.45 46.36,64.45 v46.99,63.82 | v58.1,63.82 58.1,62.5
IDE_IOR  (via drill 0.61 pad 1.6)
  Top 0.406: v79.69,34.92 v94.93,34.92 | v41.91,38.1 v46.99,38.1
  Bottom 0.406: 54.29,53.02 54.29,52.97 54.29,52.23 52.07,50.01 46.83,50.01 40.64,43.81 40.64,42.54 41.91,41.27 41.91,40.64 v41.91,38.1 | 93.34,35.51 93.4,35.51 93.5,35.4 94.46,35.4 v94.93,34.92 | v46.99,38.1 46.36,37.46 46.36,33.34 47.31,32.38 50.48,32.38 51.12,31.75 52.71,31.75 53.34,32.38 53.34,33.65 53.98,34.29 55.25,34.29 60.01,29.53 61.28,29.53 64.61,32.86 64.61,35.4 65.09,35.88 | 65.09,35.88 | 77.15,34.92 v79.69,34.92 | 65.09,35.88 76.52,35.88 77.15,35.24 77.15,34.92 | 77.15,34.92 77.15,34.72
IDE_IOW
  Bottom 0.406: 39.37,43.18 39.37,43.81 46.36,50.8 51.59,50.8 53.02,52.23 53.02,52.97 53.02,53.02
IDE_RES
  Bottom 0.406: 36.83,35.56 33.34,39.05 33.34,56.83 35.56,59.05 44.29,59.05 45.24,58.1 48.74,58.1 51.75,55.09 51.75,52.97
INT
  Bottom 0.406: 36.83,30.48 35.56,30.48 31.11,26.04 X1.
MAS_DEM
  Bottom 0.406: 66.04,85.73 67.15,85.73 69.37,83.5 69.37,74.77 63.02,68.42 56.83,68.42 52.86,64.45 49.53,64.45 47.15,62.07 47.19,62.03 R2.
MAS_SIC  (via drill 0.61 pad 1.6)
  Top 0.406: v43.18,54.29 v43.18,69.85
  Bottom 0.406: 36.83,38.1 35.88,38.1 34.29,39.69 34.29,53.02 36.51,55.24 37.78,56.51 40.96,56.51 v43.18,54.29 | 50.8,78.11 50.16,78.11 48.58,76.52 46.99,76.52 43.18,72.71 v43.18,69.85
MAS_SID  (via drill 0.61 pad 1.6)
  Top 0.406: v45.4,54.29 v45.4,69.85
  Bottom 0.406: 36.83,40.64 36.2,41.27 36.2,45.08 37.78,46.67 37.78,53.66 38.1,53.97 39.05,53.97 | 53.34,78.11 52.07,76.84 50.16,76.84 48.9,75.56 47.47,75.56 45.4,73.5 v45.4,69.85 | 39.05,53.97 39.05,55.24 | 39.05,53.97 40.01,53.97 41.27,52.7 43.82,52.7 v45.4,54.29
MCK  (via drill 0.61 pad 1.6)
  Top 0.406: v29.21,73.03 v29.21,79.38
  Bottom 0.406: 21.59,45.4 19.05,47.94 19.05,52.39 20.95,54.29 22.54,54.29 23.81,55.56 23.81,63.82 29.21,69.22 v29.21,73.03 | 35.31,87 34.29,87 33.02,85.73 33.02,83.19 v29.21,79.38
MEM_/RD  (via drill 0.61 pad 1.6)
  Top 0.406: v39.37,14.61 v51.44,14.61
  Bottom 0.406: 64.77,19.37 64.77,18.73 60.01,13.97 52.07,13.97 v51.44,14.61 | 39.37,27.94 39.37,27.3 36.2,24.13 36.2,17.14 38.73,14.61 v39.37,14.61
MEM_/WR  (via drill 0.61 pad 1.6)
  Top 0.406: v37.78,21.59 v51.75,21.59
  Bottom 0.406: v51.75,21.59 52.07,21.27 52.07,19.37 | v37.78,21.59 37.78,23.81 39.37,25.4
MEM_ALE  (via drill 0.61 pad 1.6)
  Top 0.406: v61.91,26.67 v80.33,26.67
  Bottom 0.406: 54.61,33.02 55.25,33.02 61.59,26.67 v61.91,26.67 | v80.33,26.67 91.44,26.67 93.34,24.77 93.34,23.89
MISO
  Bottom 0.406: 39.37,40.64 38.73,40.64 37.15,42.23 37.15,44.77 39.05,46.67 39.05,52.7
N$1
  Bottom 0.254: 51.75,62.5 51.75,61.59
  Bottom 0.406: 78.74,74.3 77.47,73.03 77.47,71.12 76.83,70.48 73.98,70.48 69.85,66.36 69.85,64.14 64.77,59.05 53.98,59.05 51.75,61.28 51.75,62.5
N$2
  Bottom 0.254: 53.02,62.5 53.02,61.59
  Bottom 0.406: 78.74,76.84 77.47,78.11 75.56,78.11 74.14,76.68 74.14,71.91 68.9,66.67 68.9,64.45 64.45,60.01 54.29,60.01 53.02,61.28 53.02,62.5
N$3  (via drill 0.61 pad 1.6)
  Top 0.406: v67.31,58.1 v67.31,65.09
  Bottom 0.406: 78.74,79.38 77.47,80.65 75.56,80.65 73.34,78.42 73.34,72.39 67.31,66.36 v67.31,65.09 | 64.45,54.61 60.01,54.61 59.37,53.97 59.37,52.97 | v67.31,58.1 67.31,56.83 65.09,54.61 64.45,54.61 | 64.45,54.61 R16.
N$4
  Bottom 0.406: 19.64,85.09 19.68,85.09 19.68,87.64 C1.
N$5
  Bottom 0.406: IC5. 19.68,81.28 19.68,74.92 C2.
N$6
  Bottom 0.406: R3. 17.03,87.74 16.83,87.95 R5. 16.83,88.27 20.95,92.39 20.95,93.33
N$7
  Bottom 0.406: 16.71,72.39 16.71,70.37 16.51,70.17 R6. 17.26,70.05 18.1,69.22 20.64,69.22 20.64,69.23
N$8
  Bottom 0.406: 16.83,91.01 16.83,90.96 14.29,90.96 C3. 14.29,90.49 11.11,87.31 R10.
N$9
  Bottom 0.406: 16.51,67.11 14.08,67.11 13.97,66.99 13.97,67.11 13.97,66.67 11.11,63.82 R11.
N$10
  Bottom 0.406: 65.72,44.21 65.72,49.85 70.8,54.93 70.8,61.28 76.2,66.67
N$11  (4 unrouted)
  Bottom 0.305: 67.31,92.08 67.31,92.71 | 59.37,80.96 59.37,81.6 | 25.72,87.95 25.72,88.58 | 20.95,85.73 20.95,86.36 | 20.95,76.2 20.95,76.84
N$12
  Bottom 0.406: 66.99,44.24 66.99,49.85 71.75,54.61 71.75,59.69 76.2,64.14
N$13
  Bottom 0.406: 68.26,44.24 68.26,49.85 72.71,54.29 72.71,58.1 76.2,61.59
N$14
  Bottom 0.406: 69.53,44.24 69.53,49.85 73.66,53.97 73.66,56.51 75.88,58.74 75.88,59.05 76.2,59.05
N$15
  Bottom 0.406: 70.8,44.24 70.8,49.85 74.61,53.66 74.61,55.88 75.25,56.51 76.2,56.51
N$16
  Bottom 0.406: 72.07,44.24 72.07,49.85 76.2,53.97
N$17
  Bottom 0.406: 48.26,85.73 50.8,85.73
N$18
  Bottom 0.406: 39.37,33.02 40.64,34.29 40.64,41.27 40.01,41.91 38.73,41.91 38.1,42.54 38.1,43.81 46.99,52.7 46.99,54.93 46.04,55.88 45.09,55.88 43.82,57.15 43.82,57.94 43.75,58.01 Q1.
N$19
  Bottom 0.254: 50.48,62.5 50.48,61.59
  Bottom 0.406: 78.74,46.35 77.47,47.62 77.47,67.31 76.83,67.95 72.71,67.95 70.8,66.04 70.8,63.82 65.09,58.1 53.66,58.1 50.48,61.28 50.48,62.5
N$20
  Bottom 0.406: 73.34,44.24 73.34,48.58 76.2,51.43
N$21
  Bottom 0.406: 45.78,59.09 45.78,59.15 44.45,60.48 44.45,61.28 44.25,61.48 44.25,61.59
N$22
  Bottom 0.406: R1. 48.06,95.57 36.51,95.57 34.29,93.34
N$23
  Bottom 0.406: 35.31,81.92 36.51,81.92 37.47,82.87 37.47,87 38.73,88.27 40.77,88.27
N$24
  Bottom 0.406: 76.2,48.89 75.88,48.89 74.61,47.62 74.61,44.24
N$25
  Bottom 0.406: 81.91,45.01 81.91,46.99 80.01,48.89 78.74,48.89
N$26
  Bottom 0.406: 83.18,45.03 83.18,47.62 79.38,51.43 78.74,51.43
N$27
  Bottom 0.406: 84.45,45.03 84.45,48.26 78.74,53.97
N$28
  Bottom 0.406: 85.72,45.03 85.72,49.53 78.74,56.51
N$29
  Bottom 0.406: 86.99,45.03 86.99,50.8 78.74,59.05
N$30
  Bottom 0.406: 88.27,45.03 88.27,52.07 78.74,61.59
N$31
  Bottom 0.406: 89.53,45.03 89.53,53.34 78.74,64.14
N$32
  Bottom 0.406: 90.8,45.03 90.8,54.61 78.74,66.67
N$33
  Bottom 0.406: 78.74,89.54 80.17,88.11 80.17,86.36 79.53,85.73 78.1,85.73 77.47,85.09 77.47,83.82 76.83,83.19 74.93,83.19 71.75,80.01 71.75,73.34 64.45,66.04 58.26,66.04 56.67,64.45 56.67,63.02 56.83,62.87 56.83,62.5
N$34
  Bottom 0.406: 76.2,89.54 70.17,83.5 70.17,74.3 63.5,67.63 57.31,67.63 54.29,64.61 54.29,62.5
N$35
  Bottom 0.406: 78.74,87 78.1,87 76.83,85.73 75.25,85.73 70.96,81.28 70.96,73.82 63.98,66.83 57.79,66.83 55.56,64.61 55.56,62.5
N$36  (4 unrouted)
  Bottom 0.305: 67.63,92.39 66.99,92.39 | 59.69,81.28 59.05,81.28 | 26.04,88.27 25.4,88.27 | 21.27,86.04 20.64,86.04 | 21.27,76.52 20.64,76.52
N$37
  Bottom 0.305: 49.85,35.88 49.85,36.51
N$38
  Bottom 0.406: 12.06,13.34 12.38,13.02 15.04,13.02
N$39
  Bottom 0.406: 15.04,11.75 13.02,11.75 Q2.
N$40
  Bottom 0.406: 28.26,89.22 28.26,91.44
N$41
  Bottom 0.813: 70.33,95.57 D1.
N$42
  Bottom 0.406: 25.4,37.15 23.81,38.73 R24. 23.7,38.85 23.49,39.05 19.21,39.05 19.21,39.53 19.25,39.53
N$43
  Bottom 0.61: 28.89,97.63 30.16,95.73 | 28.89,97.63 27.62,99.54 27.3,99.54 | 27.3,97.63 27.3,99.54 | 27.3,97.63 27.3,95.73 | 27.3,99.54 25.72,99.54 | 26.35,97.63 27.3,97.63 | 27.3,97.63 28.89,97.63
N$44
  Bottom 0.406: D7. 27.28,17.44 27.3,17.46 R22.
N$45
  Bottom 0.406: 25.34,43.46 24.17,43.46 24.13,43.5 23.93,43.29 23.81,43.29 23.81,41.8
N$46
  Bottom 0.61: 24.76,95.73 24.76,99.54 23.81,99.54 23.18,98.58 23.18,96.36 23.81,95.73 24.76,95.73
N$47
  Bottom 0.61: 22.22,99.54 22.22,95.73 21.27,97 20.32,95.73 20.32,99.54
N$48
  Bottom 0.61: 13.02,97 11.75,98.27
N$50
  Bottom 0.61: 10.16,97 8.89,98.27
N$51
  Bottom 0.305: 49.53,36.2 50.16,36.2
N$52
  Bottom 0.406: 13.97,83.19 12.38,81.6 6.19,81.6 6.08,81.71 5.87,81.71
N$54
  Bottom 0.406: JP6. 9.21,75.56 7.46,73.82 7.46,71.12 5.87,69.53 5.87,69.42
N$55
  Bottom 0.61: 17.14,97.63 17.14,98.9 17.78,99.54 18.41,99.54 19.05,98.9 19.05,98.27 18.41,97.63 17.14,97.63 | 17.14,97.63 17.14,96.36 17.78,95.73 18.41,95.73 19.05,96.36
N$56
  Bottom 0.406: R17. 47.62,73.18 47.62,70.48
N$57
  Bottom 0.61: 14.29,97.63 14.29,98.9 14.92,99.54 15.56,99.54 16.19,98.9 16.19,98.27 15.56,97.63 14.29,97.63 | 14.29,97.63 14.29,96.36 14.92,95.73 15.56,95.73 16.19,96.36
N$58
  Bottom 0.61: 12.7,99.54 13.34,98.9 13.34,96.36 12.7,95.73 12.06,95.73 11.43,96.36 11.43,98.9 12.06,99.54 12.7,99.54
N$59
  Bottom 0.406: 10.16,40 T1. | 10.16,40 10.16,41.07 | R91. 5.71,40 10.16,40
N$60
  Bottom 0.61: 10.48,98.9 9.84,99.54 9.21,99.54 8.57,98.9 8.57,96.36 9.21,95.73 9.84,95.73 10.48,96.36 10.48,98.9
N$61
  Bottom 0.406: R28. 27.3,45.56 27.3,44.49 Q3. 27.3,44.42 27.3,41.8 R7.
PI8
  Bottom 0.406: 58.42,75.56 58.42,74.93 56.67,73.18 53.98,73.18 51.28,70.48 V1.
RES
  Bottom 0.406: 39.37,38.1 38.1,39.37 36.2,39.37 35.24,40.32 35.24,46.2 36.04,46.99 | 36.04,46.99 | 36.04,46.99 36.51,47.47 36.51,52.7
SCK
  Bottom 0.406: 58.42,78.11 59.69,79.38 64.13,79.38 64.77,78.74 64.77,73.98 61.59,70.8 55.4,70.8 51.44,66.83 41.43,66.83 38.42,69.85 34.93,69.85 27.62,62.55 27.62,53.02 22.54,47.94 21.59,47.94
SCL  (1 unrouted)
  Bottom 0.406: 53.34,93.34 54.61,92.08 54.61,89.85 62.55,81.92 66.67,81.92 67.79,80.8 67.79,75.72 62.07,70.01 55.88,70.01 51.91,66.04 34.93,66.04 30.48,61.59 30.48,30.48 | 39.37,30.48 38.73,30.48 37.47,29.21 36.2,29.21 33.66,26.67 33.66,26.24 | 30.48,30.48 30.48,27.94 29.21,26.67 29.21,21.59 28.26,20.64 26.35,20.64 25.4,19.68 25.4,18.41 22.86,15.88 22.86,14.92 23.49,14.29 24.56,14.29 28.89,14.29 30.48,12.7 34.29,12.7 34.93,13.34 34.93,15.24 33.66,16.51 R20. | 30.48,30.48 R15.
SDA
  Bottom 0.406: 29.53,15.56 29.53,17.46 30.16,18.1 30.16,26.35 33.34,29.53 33.34,31.43 32.07,32.7 32.07,32.91 R14. 31.75,33.22 31.75,33.34 31.43,33.34 31.43,61.28 35.4,65.25 52.39,65.25 56.36,69.22 62.55,69.22 68.58,75.25 68.58,82.55 66.67,84.45 62.23,84.45 55.88,90.81 | 36.83,27.94 36.83,27.3 34.29,24.77 32.7,24.77 32.07,24.13 32.07,18.1 32.39,17.78 32.39,15.24 | 32.39,15.24 33.66,13.97 | 32.39,15.24 29.84,15.24 29.53,15.56 | 24.56,15.56 29.53,15.56
SDATA
  Bottom 0.406: 60.96,78.11 62.23,76.84 62.23,74.77 59.05,71.6 54.93,71.6 50.96,67.63 41.91,67.63 38.73,70.8 34.61,70.8 26.67,62.87 26.67,53.34 22.54,49.21 20.95,49.21 20,50.16 20,51.43 21.59,53.02 22.54,53.02 24.76,55.24 24.76,63.5 30.96,69.69 30.96,73.5 29.84,74.61 26.99,74.61 22.54,79.06 22.54,83.19 24.45,85.09 25.44,85.09
SPDIF+
  Bottom 0.61: 1.27,32.38 1.27,31.75 10.16,22.86
SPDIF-  (2 unrouted)
  Bottom 0.61: 8.26,35.56 8.26,30.48 10.16,28.57
TXP
  Bottom 0.406: 13.97,45.4 12.38,43.81 10.16,43.81 | 10.16,43.81 10.05,43.7 R90. 10.16,43.81 | 8.26,51.43 8.26,53.02 6.67,54.61 3.49,54.61 1.91,53.02 1.91,44.77 3.49,43.18 8.89,43.18 9.53,43.81 10.16,43.81
U_BATT
  Bottom 0.406: 27.94,27.94 27.94,22.23 27.62,22.23 27.51,22.11 27.3,22.11
U_RTC
  Bottom 0.406: 19.57,8.57 21.42,8.57 21.42,8.72 21.59,8.89 21.59,10.16 23.18,11.75 D3. 26.04,11.75 27.14,12.85 27.3,12.85
VCC  (via drill 0.61 pad 1.6)  (2 unrouted)
  Top 0.406: v58.1,10.48 v63.82,10.48 | v62.23,53.02 v62.23,62.55 | v26.99,73.03 v26.99,79.38 | v42.23,10.48 v50.48,10.48
  Bottom 0.254: 60.64,52.97 60.64,53.02
  Bottom 0.406: IC4. 44.45,16.83 50.48,10.79 v50.48,10.48 | 54.61,35.56 53.98,35.56 52.71,34.29 48.9,34.29 48.91,33.98 48.9,34.62 48.9,38.73 48.26,39.37 48.26,41.27 46.99,42.54 IC1. 46.99,44.45 49.37,46.83 53.98,46.83 58.42,51.28 60.64,51.28 60.64,52.97 | QG1. 41.91,78.11 38.73,78.11 38.73,81.92 | 35.24,84.45 35.31,84.39 35.31,83.19 34.29,83.19 33.66,82.55 33.66,80.65 34.29,80.01 QG1. | 35.24,84.45 35.31,84.45 | 35.31,85.73 35.31,84.52 35.24,84.45 | 40.64,85.73 40.77,85.85 40.77,87 43.18,87 43.29,87.11 43.5,87.11 43.5,87 | 40.64,85.73 40.77,85.73 | 40.64,85.73 40.77,85.6 40.77,84.45 39.37,84.45 38.73,83.82 38.73,81.92 | 38.73,81.92 40.77,81.92 | 93.34,45.08 IC6. 93.34,44.29 92.07,43.02 77.15,43.02 | v63.82,10.48 70.17,16.83 82.07,16.83 83.98,18.73 83.98,21.11 81.91,23.18 IC3. 81.86,23.86 81.39,24.33 80.01,24.33 | 74.61,96.52 74.61,93.66 76.2,92.08 | IC8. 60.75,62.5 60.8,62.55 v62.23,62.55 62.23,63.18 62.87,63.82 62.87,64.25 63.07,64.45 | 60.64,53.02 v62.23,53.02 | v26.99,79.38 28.57,77.79 29.84,77.79 30.16,78.11 QG1. | 82.87,77.79 82.98,77.67 R21. | 82.87,74.61 83.3,74.73 83.18,74.73 | 55.88,10.48 55.88,10.68 55.99,10.68 56.2,10.48 | D6. 25.74,8.57 | 29.01,33.02 28.89,32.82 28.89,31.75 | 29.01,30.48 28.89,30.68 28.89,31.75 | VR1. 26.99,35.56 26.99,38.73 26.87,38.85 26.67,38.85 | 25.08,31.75 28.89,31.75 | 12.06,47.94 11.86,47.74 11.75,47.74 11.54,47.74 11.11,47.62 | C17. 6.46,50.37 6.67,50.16 6.99,50.16 | 21.59,42.86 20.64,41.91 17.78,41.91 | 76.2,43.02 | 76.2,43.02 65.09,43.02 64.61,43.5 64.61,51.43 64.41,51.55 64.45,51.55 64.34,51.55 64.29,51.59 63.66,51.59 v62.23,53.02 | 76.2,43.02
  Bottom 0.406: v62.23,53.02 | 76.2,43.02 77.15,43.02 | 77.15,43.02 IC7.
  Bottom 0.61: 21.59,37.78 21.59,35.24 24.13,35.24 VR1. | 93.34,45.08 93.66,45.4 93.66,46.99 | 93.66,46.99 95.14,46.99 | 93.66,46.99 93.66,56.83 82.87,67.63 82.87,74.61 | 13.97,60.64 13.97,63.18 | 33.66,11.43 41.27,11.43 v42.23,10.48 | 90.8,86.36 C9. | v50.48,10.48 55.88,10.48 | 56.2,10.48 v58.1,10.48 | 12.06,47.94 13.97,47.94 | 13.97,55.56 9.84,51.75 9.84,48.89 | 9.84,48.89 8.26,48.89 6.99,50.16 | 9.84,48.89 11.11,47.62
  Bottom 0.813: 33.66,11.43 31.11,11.43 29.21,11.43 26.35,8.57 25.74,8.57 | 17.78,37.78 13.97,37.78 12.06,35.88 12.06,34.29 14.61,31.75 25.08,31.75 25.08,22.86 23.49,21.27 QG2. 18.1,19.05 | 17.78,37.78 21.59,37.78 | 16.83,55.56 13.97,55.56 | 16.83,55.56 16.83,60.64 | 16.83,60.64 13.97,60.64 | 18.1,19.05 15.88,19.05 | 82.87,86.36 82.87,93.03 79.38,96.52 74.61,96.52 72.71,98.42 66.04,98.42 | 66.04,98.42 D2. | 16.83,60.64 19.05,60.64 21.59,63.18 26.99,68.58 v26.99,73.03 | 66.04,98.42 36.51,98.42 31.11,93.03 31.11,83.82 26.99,79.69 v26.99,79.38 | 82.87,86.36 X5. 90.8,86.36 | 82.87,86.36 82.87,77.79 | 18.1,19.05 18.1,7.3 19.05,6.35 24.13,6.35 25.72,7.94 D6. | 16.83,55.56 16.83,46.35 17.78,45.4 17.78,41.91 17.78,37.78
(copper drawn outside any net)
  shapes: Bottom area x1, Bottom circle x7

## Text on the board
Bottom: +5V | L | GND | +12V | R | SPDIF | PRG | 1 | opt. | SPDIF | 75ohm | I2C
tNames: Left | Right | SPDIF | SPDIF | 75ohm
tValues: Prog | I2c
